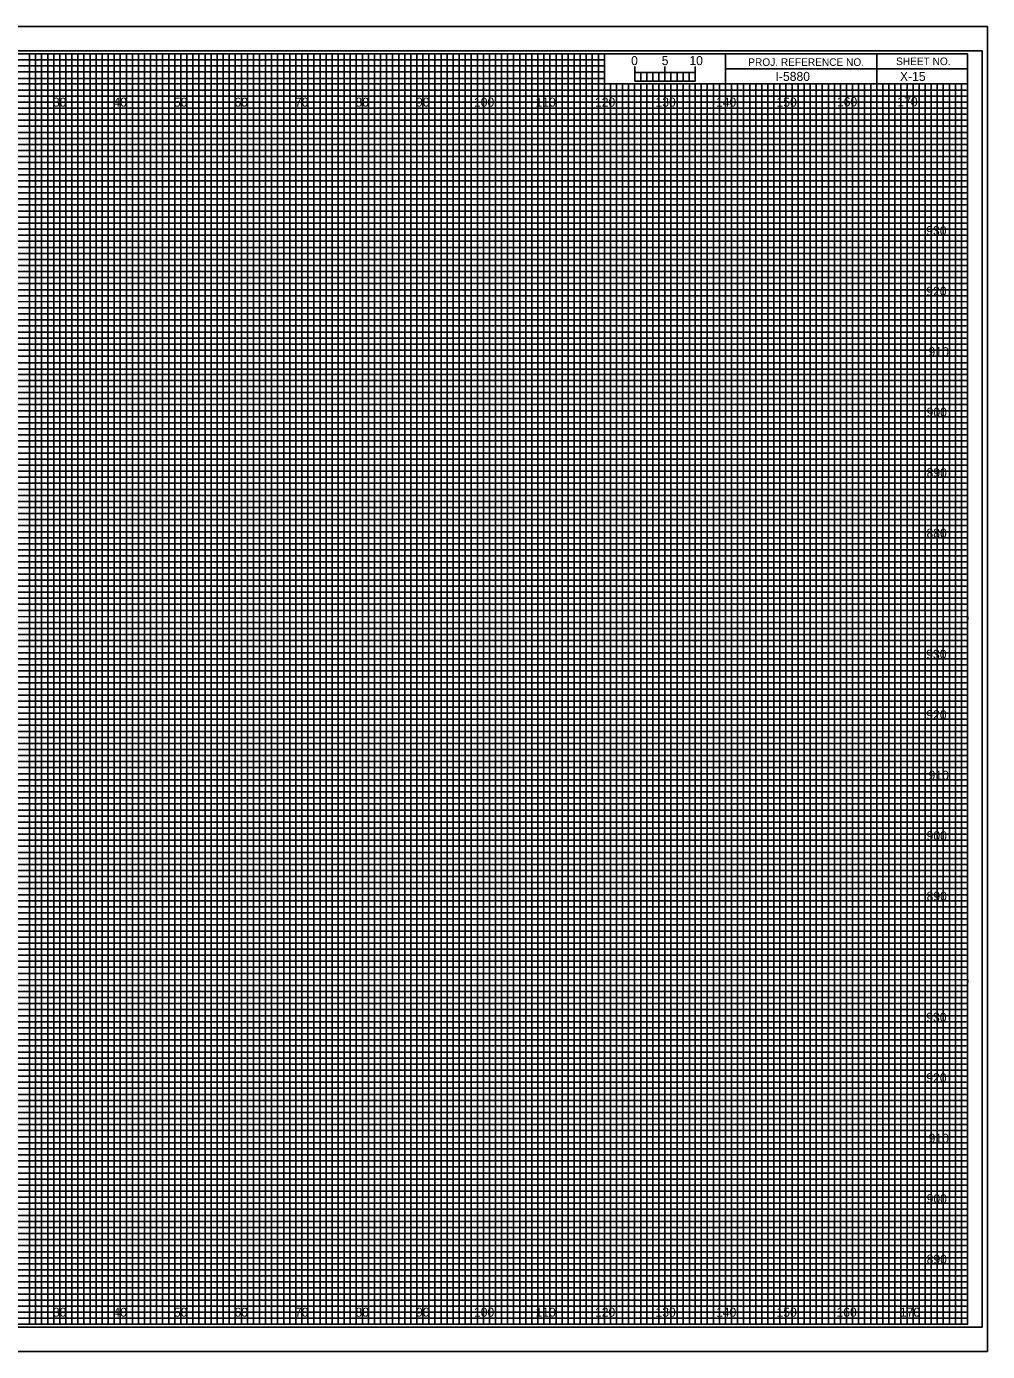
# Model space of a CAD drawing. Extents: x -13 to 323, y -4 to 3074.
# Drawn here: x 164.5 to 323.3, y 2855.5 to 3074.5 of the extents above; entities that cross this region are included whole.
import ezdxf

# ---------------------------------------------------------------- set-up
doc = ezdxf.new("R2010")
doc.units = 0
for name, color, linetype in [('Prop XS Bar Scale Labels', 7, 'Continuous'), ('Prop XS Elevation Labels', 7, 'Continuous'), ('Prop XS Offset Labels', 7, 'Continuous'), ('Prop XS Project Number', 7, 'Continuous'), ('Prop XS Sheet Number', 7, 'Continuous'), ('Sheet Cross Section CELL', 7, 'Continuous'), ('Sheet Cross Section Grid Major CELL', 7, 'Continuous'), ('Sheet Cross Section Grid Middle CELL', 7, 'Continuous'), ('Sheet Cross Section Grid Minor 1 CELL', 7, 'Continuous'), ('Sheet Cross Section Grid Minor 2 CELL', 7, 'Continuous'), ('Sheet Cross Section Scale CELL', 7, 'Continuous'), ('Sheet Cutting Line CELL', 7, 'Continuous'), ('Sheet DOT Grid CELL', 7, 'Continuous'), ('Sheet Plot Border Inside CELL', 7, 'Continuous'), ('Sheet Plot Border Outside CELL', 7, 'Continuous')]:
    doc.layers.add(name, color=color, linetype=linetype)

msp = doc.modelspace()

# ---------------------------------------------------------------- linework, layer by layer
at = {"layer": 'Sheet Cross Section CELL'}
for p, q in [((305, 3070), (305, 3065)), ((305, 3065), (305, 3070)), ((280, 3067.5), (280, 3065)), ((320, 3067.49), (280, 3067.49)), ((280, 3065), (320, 3065))]:
    msp.add_line(p, q, dxfattribs=at)
for points in [[(320, 3070), (0, 3070), (0, 2860), (320, 2860)], [(280, 3070), (260, 3070), (260, 3065.03), (280, 3065.03)], [(320, 3070), (280, 3070), (280, 3065), (320, 3065)]]:
    msp.add_lwpolyline(points, close=True, dxfattribs=at)
at = {"layer": 'Sheet Cross Section Grid Major CELL'}
for p, q in [((170, 3070), (160, 3070)), ((170, 2860), (170, 3070)), ((190, 3070), (180, 3070)), ((180, 3070), (180, 2860)), ((190, 2860), (190, 3070)), ((210, 3070), (200, 3070)), ((200, 3070), (200, 2860)), ((210, 2860), (210, 3070)), ((230, 3070), (220, 3070)), ((220, 3070), (220, 2860)), ((230, 2860), (230, 3070)), ((250, 3070), (240, 3070)), ((240, 3070), (240, 2860)), ((250, 2860), (250, 3070)), ((260, 3070), (260, 2860)), ((270, 2860), (270, 3065)), ((290, 3065), (280, 3065)), ((280, 3065), (280, 2860)), ((290, 2860), (290, 3065)), ((310, 3065), (300, 3065)), ((300, 3065), (300, 2860)), ((310, 2860), (310, 3065)), ((180, 2860), (170, 2860)), ((200, 2860), (190, 2860)), ((220, 2860), (210, 2860)), ((240, 2860), (230, 2860)), ((260, 2860), (250, 2860)), ((280, 2860), (270, 2860)), ((300, 2860), (290, 2860)), ((320, 2860), (310, 2860)), ((320, 2860), (320, 2860))]:
    msp.add_line(p, q, dxfattribs=at)
for points in [[(0, 3060), (320, 3060), (320, 3050), (0, 3050)], [(0, 3040), (320, 3040), (320, 3030), (0, 3030)], [(0, 3020), (320, 3020), (320, 3010), (0, 3010)], [(0, 3000), (320, 3000), (320, 2990), (0, 2990)], [(0, 2980), (320, 2980), (320, 2970), (0, 2970)], [(0, 2960), (320, 2960), (320, 2950), (0, 2950)], [(0, 2940), (320, 2940), (320, 2930), (0, 2930)], [(0, 2920), (320, 2920), (320, 2910), (0, 2910)], [(0, 2900), (320, 2900), (320, 2890), (0, 2890)], [(0, 2880), (320, 2880), (320, 2870), (0, 2870)]]:
    msp.add_lwpolyline(points, dxfattribs=at)
at = {"layer": 'Sheet Cross Section Grid Middle CELL'}
for points in [[(155, 3070), (165, 3070), (165, 2860), (175, 2860), (175, 3070), (185, 3070), (185, 2860), (195, 2860), (195, 3070), (205, 3070), (205, 2860), (215, 2860), (215, 3070), (225, 3070), (225, 2860), (235, 2860), (235, 3070), (245, 3070), (245, 2860), (255, 2860), (255, 3070), (259.93, 3070), (260, 3070), (260, 3065), (264.99, 3065), (264.99, 2860), (275, 2860), (275, 3065), (285, 3065), (285, 2860), (295, 2860), (295, 3065), (305, 3065), (305, 2860), (315, 2860), (315, 3065)], [(0, 3065), (275, 3065)], [(0, 3045), (320, 3045), (320, 3055), (0, 3055)], [(0, 3025), (320, 3025), (320, 3035), (0, 3035)], [(0, 3005), (320, 3005), (320, 3015), (0, 3015)], [(0, 2985), (320, 2985), (320, 2995), (0, 2995)], [(0, 2965), (320, 2965), (320, 2975), (0, 2975)], [(0, 2945), (320, 2945), (320, 2955), (0, 2955)], [(0, 2925), (320, 2925), (320, 2935), (0, 2935)], [(0, 2905), (320, 2905), (320, 2915), (0, 2915)], [(0, 2885), (320, 2885), (320, 2895), (0, 2895)], [(0, 2865), (320, 2865), (320, 2875), (0, 2875)]]:
    msp.add_lwpolyline(points, dxfattribs=at)
at = {"layer": 'Sheet Cross Section Grid Minor 1 CELL'}
for p, q in [((0, 3069), (260, 3069)), ((260, 3069), (260, 3067.98)), ((260, 3067.98), (0, 3067.98)), ((0, 3067), (260, 3067)), ((260, 3067), (260, 3065.89)), ((260, 3065.89), (0, 3065.89)), ((0, 3064), (320, 3064))]:
    msp.add_line(p, q, dxfattribs=at)
for points in [[(0, 3063), (270, 3063), (320, 3063), (320, 3062), (0, 3062)], [(0, 3061), (320, 3061), (320, 3059), (0, 3059)], [(0, 3058), (320, 3058), (320, 3057), (0, 3056.98)], [(0, 3056), (320, 3056), (320, 3054), (0, 3054)], [(0, 3053), (320, 3053), (320, 3052), (0, 3052)], [(0, 3051), (320, 3051), (320, 3049), (0, 3049)], [(0, 3048), (320, 3048), (320, 3047), (0, 3047)], [(0, 3046), (320, 3046), (320, 3044), (0, 3044)], [(0, 3043), (320, 3043), (320, 3042), (0, 3042)], [(0, 3041), (320, 3041), (320, 3039), (0, 3039)], [(0, 3038), (320, 3038), (320, 3037), (0, 3037)], [(0, 3036), (320, 3036), (320, 3033.95), (320, 3033), (320, 3032), (0, 3032)], [(0, 3034), (320, 3034), (320, 3033), (0, 3033)], [(0, 3031), (320, 3031), (320, 3029), (0, 3029.03)], [(0, 3029.03), (320, 3029), (320, 3028), (0, 3028)], [(0, 3027), (320, 3027), (320, 3026), (0, 3026)], [(0, 3024), (320, 3024), (320, 3023), (0, 3023)], [(0, 3022), (320, 3022), (320, 3021), (0, 3021)], [(-0.07, 3018.89), (320, 3018.89), (320, 3017.88), (-0.07, 3017.88)], [(0, 3017), (320, 3017), (320, 3016), (0, 3016)], [(0, 3014), (320, 3014), (320, 3013), (0, 3013)], [(0, 3012), (320, 3012), (320, 3011), (0, 3011)], [(0, 3009), (320, 3009), (320, 3008), (0, 3008)], [(0, 3007), (320, 3007), (320, 3006), (0, 3006)], [(0, 3004), (320, 3004), (320, 3003), (0, 3003)], [(0, 3002), (320, 3002), (320, 3001), (0, 3001)], [(0, 2999), (320, 2999), (319.99, 2997.98), (0, 2998)], [(0, 2997), (320, 2997), (320, 2996), (0, 2996)], [(0, 2994), (320, 2994), (320, 2993), (0, 2993)], [(0, 2992), (320, 2992), (320, 2991), (0, 2991)], [(0, 2989), (320, 2989), (320, 2988), (0, 2988)], [(0, 2987), (320, 2987), (320, 2986), (0, 2986)], [(0, 2984), (320, 2984), (320, 2983), (0, 2983)], [(0, 2982), (320, 2982), (320, 2981), (0, 2981)], [(0, 2979), (320, 2979), (320, 2978), (0, 2978)], [(0, 2976.99), (320.07, 2976.91), (320, 2976), (0, 2976)], [(0, 2974), (320, 2974), (320, 2973), (0, 2973)], [(0, 2972), (320, 2972), (320, 2971), (0, 2971)], [(0, 2969), (320, 2969), (320, 2968), (0, 2968)], [(0, 2967), (320, 2967), (320, 2966), (0, 2966)], [(0, 2964), (320, 2964), (320, 2963), (0, 2963)], [(0, 2962), (320, 2962), (320, 2961), (0, 2961)], [(0, 2959), (320, 2959), (320, 2958), (0, 2958)], [(0, 2957), (320, 2957), (320, 2956), (0, 2956)], [(0, 2954), (320, 2954), (320, 2953), (0, 2953)], [(0, 2952), (320, 2952), (320, 2951), (0, 2951)], [(0, 2949), (320, 2949), (320, 2948), (0, 2948)], [(0, 2947), (320, 2947), (320, 2946), (0, 2946)], [(0, 2944), (320, 2944), (320, 2943), (0, 2943)], [(0, 2942), (320, 2942), (320, 2941), (0, 2941)], [(0, 2939), (320, 2939), (319.99, 2937.98), (0, 2938)], [(0, 2937), (320, 2937), (320, 2936), (0, 2936)], [(0, 2934), (320, 2934), (320, 2933), (0, 2933)], [(0, 2932), (320, 2932), (320, 2931), (0, 2931)], [(0, 2929), (320, 2929), (320, 2928), (0, 2928)], [(0, 2927), (320, 2927), (320, 2926), (0, 2926)], [(0, 2924), (320, 2924), (320, 2923), (0, 2923)], [(0, 2922), (320, 2922), (320, 2921), (0, 2921)], [(0, 2919), (320, 2919), (320, 2918), (0, 2918)], [(0, 2916.99), (320.07, 2916.91), (320, 2916), (0, 2916)], [(0, 2914), (320, 2914), (320, 2913), (0, 2913)], [(0, 2912), (320, 2912), (320, 2911), (0, 2911)], [(0, 2909), (320, 2909), (320, 2908), (0, 2908)], [(0, 2907), (320, 2907), (320, 2906), (0, 2906)], [(0, 2904), (320, 2904), (320, 2903), (0, 2903)], [(0, 2902), (320, 2902), (320, 2901), (0, 2901)], [(0, 2899), (320, 2899), (320, 2898), (0, 2898)], [(0, 2897), (320, 2897), (320, 2896), (0, 2896)], [(0, 2894), (320, 2894), (320, 2893), (0, 2893)], [(0, 2892), (320, 2892), (320, 2891), (0, 2891)], [(0, 2889), (320, 2889), (320, 2888), (0, 2888)], [(0, 2887), (320, 2887), (320, 2886), (0, 2886)], [(0, 2884), (320, 2884), (320, 2883), (0, 2883)], [(0, 2882), (320, 2882), (320, 2881), (0, 2881)], [(0, 2879), (320, 2879), (320, 2878), (0, 2878)], [(0, 2877), (320, 2877), (320, 2876), (0, 2876)], [(0, 2874), (320, 2874), (320, 2873), (0, 2873)], [(0, 2872), (320, 2872), (320, 2871), (0, 2871)], [(0, 2869), (320, 2869), (320, 2868), (0, 2868)], [(0, 2867), (320, 2867), (320, 2866), (0, 2866)], [(0, 2864), (320, 2864), (320, 2863), (0, 2863)], [(0, 2862), (320, 2862), (320, 2861), (0, 2861)]]:
    msp.add_lwpolyline(points, dxfattribs=at)
at = {"layer": 'Sheet Cross Section Grid Minor 2 CELL'}
for p, q in [((267, 3065), (266.01, 3065)), ((266.01, 3065), (266.01, 2860)), ((267, 2860), (267, 3065)), ((269, 3065), (268, 3065)), ((268, 3065), (268, 2860)), ((269, 2860), (269, 3065)), ((266.01, 2860), (265, 2860)), ((268, 2860), (267, 2860))]:
    msp.add_line(p, q, dxfattribs=at)
for points in [[(165, 2860), (166, 2860), (166, 3070), (167, 3070), (167, 2860)], [(167, 2860), (168, 2860), (168, 3070), (169, 3070), (169, 2860)], [(170, 2860), (171, 2860), (171, 3070), (172, 3070), (172, 2860)], [(172, 2860), (173, 2860), (173, 3070), (174, 3070), (174, 2860)], [(175, 2860), (176, 2860), (176, 3070), (177, 3070), (177, 2860)], [(177, 2860), (178, 2860), (178, 3070), (179, 3070), (179, 2860)], [(180, 2860), (181, 2860), (181, 3070), (182, 3070), (182, 2860)], [(182, 2860), (183, 2860), (183, 3070), (184, 3070), (184, 2860)], [(185, 2860), (186, 2860), (186, 3070), (187, 3070), (187, 2860)], [(187, 2860), (188, 2860), (188, 3070), (189, 3070), (189, 2860)], [(190, 2860), (191, 2860), (191, 3070), (192, 3070), (192, 2860)], [(192, 2860), (193, 2860), (193, 3070), (194, 3070), (194, 2860)], [(195, 2860), (196, 2860), (196, 3070), (197, 3070), (197, 2860)], [(197, 2860), (198, 2860), (198, 3070), (199, 3070), (199, 2860)], [(200, 2860), (201, 2860), (201, 3070), (202, 3070), (202, 2860)], [(202, 2860), (203, 2860), (203, 3070), (204, 3070), (204, 2860)], [(205, 2860), (206, 2860), (206, 3070), (207, 3070), (207, 2860)], [(207, 2860), (208, 2860), (208, 3070), (209, 3070), (209, 2860)], [(210, 2860), (211, 2860), (211, 3070), (212, 3070), (212, 2860)], [(212, 2860), (213, 2860), (213, 3070), (214, 3070), (214, 2860)], [(215, 2860), (216, 2860), (216, 3070), (217, 3070), (217, 2860)], [(217, 2860), (218, 2860), (218, 3070), (219, 3070), (219, 2860)], [(220, 2860), (221, 2860), (221, 3070), (222, 3070), (222, 2860)], [(222, 2860), (223, 2860), (223, 3070), (224, 3070), (224, 2860)], [(225, 2860), (226, 2860), (226, 3070), (227, 3070), (227, 2860)], [(227, 2860), (228, 2860), (228, 3070), (229, 3070), (229, 2860)], [(230, 2860), (231, 2860), (231, 3070), (232, 3070), (232, 2860)], [(232, 2860), (233, 2860), (233, 3070), (234, 3070), (234, 2860)], [(235, 2860), (236, 2860), (236, 3070), (237, 3070), (237, 2860)], [(237, 2860), (238, 2860), (238, 3070), (239, 3070), (239, 2860)], [(240, 2860), (241, 2860), (241, 3070), (242, 3070), (242, 2860)], [(242, 2860), (243, 2860), (243, 3070), (244, 3070), (244, 2860)], [(245, 2860), (246, 2860), (246, 3070), (247, 3070), (247, 2860)], [(247, 2860), (248, 2860), (248, 3070), (249, 3070), (249, 2860)], [(250, 2860), (251, 2860), (251, 3070), (252, 3070), (252, 2860)], [(252, 2860), (253, 2860), (253, 3070), (254, 3070), (254, 2860)], [(255, 2860), (256, 2860), (256, 3070), (257, 3070), (257, 2860)], [(257, 2860), (258, 2860), (258, 3070), (259, 3070), (259, 2860)], [(260, 2860), (261, 2860), (261, 3065), (262.02, 3065), (262.02, 2860)], [(262, 2860), (263, 2860), (263, 3065), (263.99, 3065), (263.99, 2860)], [(270, 2860), (270.98, 2860), (270.98, 3065), (272, 3065), (272, 2860)], [(272, 2860), (273, 2860), (273, 3065), (274.05, 3065), (274.05, 2860)], [(275, 2860), (276, 2860), (276, 3065), (277, 3065), (277, 2860)], [(277, 2860), (278, 2860), (278, 3065), (279, 3065), (279, 2860)], [(280, 2860), (281, 2860), (281, 3065), (282, 3065), (282, 2860)], [(282, 2860), (283, 2860), (283, 3065), (284, 3065), (284, 2860)], [(285, 2860), (286, 2860), (286, 3065), (287, 3065), (287, 2860)], [(287, 2860), (288, 2860), (288, 3065), (289, 3065), (289, 2860)], [(290, 2860), (291, 2860), (291, 3065), (292, 3065), (292, 2860)], [(292, 2860), (293, 2860), (293, 3065), (294, 3065), (294, 2860)], [(295, 2860), (296, 2860), (296, 3065), (297, 3065), (297, 2860)], [(297, 2860), (298, 2860), (298, 3065), (299, 3065), (299, 2860)], [(300, 2860), (301, 2860), (301, 3065), (302, 3065), (302, 2860)], [(302, 2860), (303, 2860), (303, 3065), (304, 3065), (304, 2860)], [(305, 2860), (306, 2860), (306, 3065), (307, 3065), (307, 2860)], [(307, 2860), (308, 2860), (308, 3065), (309, 3065), (309, 2860)], [(310, 2860), (311, 2860), (311, 3065), (312, 3065), (312, 2860)], [(312, 2860), (313, 2860), (313, 3065), (314, 3065), (314, 2860)], [(315, 2860), (316, 2860), (316, 3065), (317, 3065), (317, 2860)], [(317, 2860), (318, 2860), (318, 3065), (319, 3065), (319, 2860)]]:
    msp.add_lwpolyline(points, dxfattribs=at)
at = {"layer": 'Sheet Cross Section Scale CELL'}
for p, q in [((265, 3065.49), (265, 3067.9)), ((265, 3066.9), (265, 3067.9)), ((270, 3065.49), (270, 3067.9)), ((275, 3065.49), (275, 3067.9)), ((275, 3066.9), (275, 3067.9))]:
    msp.add_line(p, q, dxfattribs=at)
for points in [[(275, 3066.9), (265, 3066.9), (265, 3065.49), (275, 3065.49)], [(265, 3066.9), (266, 3066.9), (266, 3065.49), (265, 3065.49)], [(267, 3066.9), (268, 3066.9), (268, 3065.49), (267, 3065.49)], [(269, 3066.9), (270, 3066.9), (270, 3065.49), (269, 3065.49)], [(271, 3066.9), (272, 3066.9), (272, 3065.49), (271, 3065.49)], [(273, 3066.9), (274, 3066.9), (274, 3065.49), (273, 3065.49)]]:
    msp.add_lwpolyline(points, close=True, dxfattribs=at)
at = {"layer": 'Sheet Cutting Line CELL'}
for p, q in [((323.3, 3074.5), (-13.4, 3074.5)), ((-13.4, 2855.5), (323.3, 2855.5))]:
    msp.add_line(p, q, dxfattribs=at)
at = {"layer": 'Sheet DOT Grid CELL'}
for p, q in [((170, 2860), (170, 3070)), ((180, 2860), (180, 3070)), ((190, 2860), (190, 3070)), ((200, 2860), (200, 3070)), ((210, 2860), (210, 3070)), ((220, 2860), (220, 3070)), ((230, 2860), (230, 3070)), ((240, 2860), (240, 3070)), ((250, 2860), (250, 3070)), ((260, 2860), (260, 3064.69)), ((270, 2860), (270, 3064.69)), ((280, 2860), (280, 3064.69)), ((290, 2860), (290, 3064.69)), ((300, 2860), (300, 3064.69)), ((310, 2860), (310, 3064.69)), ((0, 3060), (320, 3060)), ((0, 3050), (320, 3050)), ((0, 3040), (320, 3040)), ((0, 3030), (320, 3030)), ((0, 3020), (320, 3020)), ((0, 3010), (320, 3010)), ((0, 3000), (320, 3000)), ((0, 2990), (320, 2990)), ((0, 2980), (320, 2980)), ((0, 2970), (320, 2970)), ((0, 2960), (320, 2960)), ((0, 2950), (320, 2950)), ((0, 2940), (320, 2940)), ((0, 2930), (320, 2930)), ((0, 2920), (320, 2920)), ((0, 2910), (320, 2910)), ((0, 2900), (320, 2900)), ((0, 2890), (320, 2890)), ((0, 2880), (320, 2880)), ((0, 2870), (320, 2870))]:
    msp.add_line(p, q, dxfattribs=at)
at = {"layer": 'Sheet Plot Border Inside CELL'}
msp.add_lwpolyline([(-10.8, 2859.5), (322.4, 2859.5), (322.4, 3070.5), (-10.8, 3070.5)], close=True, dxfattribs=at)
at = {"layer": 'Sheet Plot Border Outside CELL'}
msp.add_lwpolyline([(-13.4, 2855.5), (323.3, 2855.5), (323.3, 3074.5), (-13.4, 3074.5)], close=True, dxfattribs=at)

# ---------------------------------------------------------------- texts
at = {"layer": 'Prop XS Bar Scale Labels'}
for s, p in [('5', (269.47, 3068.12)), ('10', (274.04, 3068.12))]:
    msp.add_text(s, height=1.5, dxfattribs=at).set_placement(p)
at = {"layer": 'Prop XS Elevation Labels'}
for s, p in [('930', (313.18, 3040)), ('920', (313.19, 3030)), ('910', (313.57, 3020)), ('900', (313.24, 3010)), ('890', (313.24, 3000)), ('880', (313.22, 2990)), ('930', (313.18, 2970)), ('920', (313.19, 2960)), ('910', (313.57, 2950)), ('900', (313.24, 2940)), ('890', (313.24, 2930)), ('930', (313.18, 2910)), ('920', (313.19, 2900)), ('910', (313.57, 2890)), ('900', (313.24, 2880)), ('890', (313.24, 2870))]:
    msp.add_text(s, height=1.5, dxfattribs=at).set_placement(p)
at = {"layer": 'Prop XS Offset Labels'}
for s, p in [('30', (168.86, 3061.25)), ('40', (178.86, 3061.25)), ('50', (188.86, 3061.25)), ('60', (198.86, 3061.25)), ('70', (208.86, 3061.25)), ('80', (218.86, 3061.25)), ('90', (228.86, 3061.25)), ('100', (238.44, 3061.25)), ('110', (248.62, 3061.25)), ('120', (258.44, 3061.25)), ('130', (268.44, 3061.25)), ('140', (278.44, 3061.25)), ('150', (288.44, 3061.25)), ('160', (298.42, 3061.31)), ('170', (308.4, 3061.31)), ('30', (168.86, 2861.25)), ('40', (178.86, 2861.25)), ('50', (188.86, 2861.25)), ('60', (198.86, 2861.25)), ('70', (208.86, 2861.25)), ('80', (218.86, 2861.25)), ('90', (228.86, 2861.25)), ('100', (238.44, 2861.25)), ('110', (248.62, 2861.25)), ('120', (258.44, 2861.25)), ('130', (268.44, 2861.25)), ('140', (278.44, 2861.25)), ('150', (288.44, 2861.25)), ('160', (298.35, 2861.25)), ('170', (308.83, 2861.25))]:
    msp.add_text(s, height=1.5, dxfattribs=at).set_placement(p)
at = {"layer": 'Prop XS Project Number'}
msp.add_text('I-5880', height=1.5, dxfattribs=at).set_placement((288.28, 3065.5))
at = {"layer": 'Prop XS Sheet Number'}
msp.add_text('X-15', height=1.5, dxfattribs=at).set_placement((308.83, 3065.5))
at = {"layer": 'Sheet Cross Section CELL'}
for s, p in [('PROJ. REFERENCE NO.', (283.77, 3067.99)), ('SHEET NO.', (308.19, 3068.12))]:
    msp.add_text(s, height=1.25, dxfattribs=at).set_placement(p)
at = {"layer": 'Sheet Cross Section Scale CELL'}
msp.add_text('0', height=1.5, dxfattribs=at).set_placement((264.41, 3068.12))

doc.saveas('drawing.dxf')
